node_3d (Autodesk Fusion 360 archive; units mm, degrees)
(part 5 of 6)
sketch "Sketch23" plane through (0, 0, 1.6) normal (0, 0, 1) x axis (-1, 0, 0)
  line L1 (157.1, 69.25) -> (157.1, 89.25)
  line L2 (155.91, 69.25) -> (157.1, 69.25)
  line L3 (155.5, 35.85) -> (155.5, 68.84)
  line L4 (196.59, 27.75) -> (163.6, 27.75)
  line L5 (197, 29.35) -> (197, 28.16)
  line L6 (217, 29.35) -> (197, 29.35)
  line L7 (217, 28.16) -> (217, 29.35)
  line L8 (250.4, 27.75) -> (217.41, 27.75)
  line L9 (258.5, 68.84) -> (258.5, 35.85)
  line L10 (256.9, 69.25) -> (258.09, 69.25)
  line L11 (256.9, 89.25) -> (256.9, 69.25)
  line L12 (258.09, 89.25) -> (256.9, 89.25)
  line L13 (258.5, 122.65) -> (258.5, 89.66)
  line L14 (217.41, 130.75) -> (250.4, 130.75)
  line L15 (217, 129.15) -> (217, 130.34)
  line L16 (197, 129.15) -> (217, 129.15)
  line L17 (197, 130.34) -> (197, 129.15)
  line L18 (163.6, 130.75) -> (196.59, 130.75)
  line L19 (155.5, 89.66) -> (155.5, 122.65)
  line L20 (157.1, 89.25) -> (155.91, 89.25)
  line L21 (208.2, 66.96) -> (208.2, 67.96)
  line L22 (211.35, 66.96) -> (208.2, 66.96)
  line L23 (211.35, 67.96) -> (211.35, 66.96)
  line L24 (208.2, 67.96) -> (211.35, 67.96)
  line L25 (208.2, 69.5) -> (208.2, 70.5)
  line L26 (211.35, 69.5) -> (208.2, 69.5)
  line L27 (211.35, 70.5) -> (211.35, 69.5)
  line L28 (208.2, 70.5) -> (211.35, 70.5)
  line L29 (208.2, 72.04) -> (208.2, 73.04)
  line L30 (211.35, 72.04) -> (208.2, 72.04)
  line L31 (211.35, 73.04) -> (211.35, 72.04)
  line L32 (208.2, 73.04) -> (211.35, 73.04)
  line L33 (204.71, 66.444) -> (204.964, 66.19)
  line L34 (204.964, 66.19) -> (209.536, 66.19)
  line L35 (204.71, 67.14) -> (204.71, 66.444)
  line L36 (204.71, 68.476) -> (204.71, 67.78)
  line L37 (204.964, 68.73) -> (204.71, 68.476)
  line L38 (204.71, 68.984) -> (204.964, 68.73)
  line L39 (204.71, 69.68) -> (204.71, 68.984)
  line L40 (204.71, 71.016) -> (204.71, 70.32)
  line L41 (204.964, 71.27) -> (204.71, 71.016)
  line L42 (204.71, 71.524) -> (204.964, 71.27)
  line L43 (204.71, 72.22) -> (204.71, 71.524)
  line L44 (204.71, 73.556) -> (204.71, 72.86)
  line L45 (204.964, 73.81) -> (204.71, 73.556)
  line L46 (209.536, 73.81) -> (204.964, 73.81)
  line L47 (209.79, 73.556) -> (209.536, 73.81)
  line L48 (209.79, 72.86) -> (209.79, 73.556)
  line L49 (209.79, 71.524) -> (209.79, 72.22)
  line L50 (209.536, 71.27) -> (209.79, 71.524)
  line L51 (209.79, 71.016) -> (209.536, 71.27)
  line L52 (209.79, 70.32) -> (209.79, 71.016)
  line L53 (209.79, 68.984) -> (209.79, 69.68)
  line L54 (209.536, 68.73) -> (209.79, 68.984)
  line L55 (209.79, 68.476) -> (209.536, 68.73)
  line L56 (209.79, 67.78) -> (209.79, 68.476)
  line L57 (209.79, 66.444) -> (209.79, 67.14)
  line L58 (209.536, 66.19) -> (209.79, 66.444)
  line L59 (203.64, 69.68) -> (204.71, 69.68)
  line L60 (203.64, 70.32) -> (204.71, 70.32)
  line L61 (210.86, 69.68) -> (209.79, 69.68)
  line L62 (210.86, 70.32) -> (209.79, 70.32)
  line L63 (210.86, 67.14) -> (209.79, 67.14)
  line L64 (210.86, 67.78) -> (209.79, 67.78)
  line L65 (203.64, 67.78) -> (204.71, 67.78)
  line L66 (203.64, 67.14) -> (204.71, 67.14)
  line L67 (203.64, 72.86) -> (204.71, 72.86)
  line L68 (203.64, 72.22) -> (204.71, 72.22)
  line L69 (210.86, 72.22) -> (209.79, 72.22)
  line L70 (210.86, 72.86) -> (209.79, 72.86)
  line L71 (203.48, 69.84) -> (203.64, 69.68)
  line L72 (203.48, 70.16) -> (203.64, 70.32)
  line L73 (211.02, 69.84) -> (210.86, 69.68)
  line L74 (210.86, 70.32) -> (211.02, 70.16)
  line L75 (211.02, 67.3) -> (210.86, 67.14)
  line L76 (210.86, 67.78) -> (211.02, 67.62)
  line L77 (203.48, 67.62) -> (203.64, 67.78)
  line L78 (203.48, 67.3) -> (203.64, 67.14)
  line L79 (203.48, 72.7) -> (203.64, 72.86)
  line L80 (203.48, 72.38) -> (203.64, 72.22)
  line L81 (211.02, 72.38) -> (210.86, 72.22)
  line L82 (210.86, 72.86) -> (211.02, 72.7)
  line L83 (203.48, 70.16) -> (203.48, 69.84)
  line L84 (211.02, 70.16) -> (211.02, 69.84)
  line L85 (211.02, 67.62) -> (211.02, 67.3)
  line L86 (203.48, 67.62) -> (203.48, 67.3)
  line L87 (203.48, 72.7) -> (203.48, 72.38)
  line L88 (211.02, 72.7) -> (211.02, 72.38)
  line L89 (203.15, 66.96) -> (203.15, 67.96)
  line L90 (206.3, 66.96) -> (203.15, 66.96)
  line L91 (206.3, 67.96) -> (206.3, 66.96)
  line L92 (203.15, 67.96) -> (206.3, 67.96)
  line L93 (203.15, 69.5) -> (203.15, 70.5)
  line L94 (206.3, 69.5) -> (203.15, 69.5)
  line L95 (206.3, 70.5) -> (206.3, 69.5)
  line L96 (203.15, 70.5) -> (206.3, 70.5)
  line L97 (203.15, 72.04) -> (203.15, 73.04)
  line L98 (206.3, 72.04) -> (203.15, 72.04)
  line L99 (206.3, 73.04) -> (206.3, 72.04)
  line L100 (203.15, 73.04) -> (206.3, 73.04)
  line L101 (157.1, 79.25) -> (256.9, 79.25)
  line L102 (207, 29.35) -> (207, 129.15)
  line L103 (189, 97.25) -> (225, 97.25)
  line L104 (189, 61.25) -> (189, 97.25)
  line L105 (225, 61.25) -> (189, 61.25)
  line L106 (225, 97.25) -> (225, 61.25)
  line L107 (189, 61.25) -> (225, 97.25)
  line L108 (225, 61.25) -> (189, 97.25)
  arc A1 centre (155.91, 68.84) radius 0.41 clockwise from (155.5, 68.84) to (155.91, 69.25)
  arc A2 centre (163.6, 35.85) radius 8.1 clockwise from (163.6, 27.75) to (155.5, 35.85)
  arc A3 centre (196.59, 28.16) radius 0.41 clockwise from (197, 28.16) to (196.59, 27.75)
  arc A4 centre (217.41, 28.16) radius 0.41 clockwise from (217.41, 27.75) to (217, 28.16)
  arc A5 centre (250.4, 35.85) radius 8.1 clockwise from (258.5, 35.85) to (250.4, 27.75)
  arc A6 centre (258.09, 68.84) radius 0.41 clockwise from (258.09, 69.25) to (258.5, 68.84)
  arc A7 centre (258.09, 89.66) radius 0.41 clockwise from (258.5, 89.66) to (258.09, 89.25)
  arc A8 centre (250.4, 122.65) radius 8.1 clockwise from (250.4, 130.75) to (258.5, 122.65)
  arc A9 centre (217.41, 130.34) radius 0.41 clockwise from (217, 130.34) to (217.41, 130.75)
  arc A10 centre (196.59, 130.34) radius 0.41 clockwise from (196.59, 130.75) to (197, 130.34)
  arc A11 centre (163.6, 122.65) radius 8.1 clockwise from (155.5, 122.65) to (163.6, 130.75)
  arc A12 centre (155.91, 89.66) radius 0.41 clockwise from (155.91, 89.25) to (155.5, 89.66)
  point P126 (256.9, 79.25)
  point P127 (157.1, 79.25)
  point P128 (207, 129.15)
  point P129 (207, 29.35)
  point P134 (207, 79.25)
  point P132 (189, 61.25)
  point P133 (225, 61.25)
  point P131 (189, 97.25)
  midpoint L11 P126
  midpoint L1 P127
  midpoint L16 P128
  midpoint L6 P129
  horizontal L103
  perpendicular L103 L104
  parallel L103 L105
  parallel L104 L106
  coincident L107 P134
  coincident L108 P134
  midpoint L101 P134
  dimension "d255" distance P132 P133 = 36
  dimension "d256" distance P131 P132 = 36
extrude "Extrude14" new body sketch "body" profile of L1 L2 A1 L3 A2 L4 A3 L5 L6 L7 A4 L8 A5 L9 A6 L10 L11 L12 A7 L13 A8 L14 A9 L15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 along normal blind 20 and against normal blind 8
shell "Shell4" innerThickness 1.5
sketch "supporttoppcb" plane through (0, 0, 0) normal (0, 0, 1) x axis (1, 0, 0)
  line L1 (-258.5, -124.25) -> (-258.5, -34.25)
  line L2 (-159.5, -128.25) -> (-254.5, -128.25)
  line L3 (-155.5, -34.25) -> (-155.5, -124.25)
  line L4 (-254.5, -30.25) -> (-159.5, -30.25)
  line L5 (-163.6, -27.25) -> (-250.4, -27.25)
  line L6 (-155, -122.65) -> (-155, -35.85)
  line L7 (-250.4, -131.25) -> (-163.6, -131.25)
  line L8 (-259, -35.85) -> (-259, -122.65)
  line L9 (-260.5, -122.65) -> (-260.5, -35.85)
  line L10 (-163.6, -132.75) -> (-250.4, -132.75)
  line L11 (-153.5, -35.85) -> (-153.5, -122.65)
  line L12 (-250.4, -25.75) -> (-163.6, -25.75)
  line L13 (-253.0634, -35.85) -> (-253.0634, -122.65)
  line L14 (-163.6, -33.1866) -> (-250.4, -33.1866)
  line L15 (-160.9366, -122.65) -> (-160.9366, -35.85)
  line L16 (-250.4, -125.3134) -> (-163.6, -125.3134)
  line L17 (-259, -41.9011) -> (-253.0634, -41.9011)
  line L18 (-155, -41.9011) -> (-160.9366, -41.9011)
  line L19 (-160.9366, -79.25) -> (-253.0634, -79.25)
  line L20 (-259, -116.5989) -> (-253.0634, -116.5989)
  line L21 (-155, -116.5989) -> (-160.9366, -116.5989)
  line L22 (-253.0634, -79.25) -> (-259, -79.25)
  line L23 (-253.0634, -66.2577) -> (-259, -66.2577)
  line L24 (-253.0634, -92.2423) -> (-259, -92.2423)
  line L25 (-207, -35) -> (-207, -33.1866)
  line L26 (-207, -125.3134) -> (-207, -35)
  line L27 (-160.9366, -66.2577) -> (-155, -66.2577)
  line L28 (-160.9366, -92.2423) -> (-155, -92.2423)
  line L29 (-256, -35.85) -> (-256, -122.65)
  line L30 (-163.6, -30.25) -> (-250.4, -30.25)
  line L31 (-158, -122.65) -> (-158, -35.85)
  line L32 (-250.4, -128.25) -> (-163.6, -128.25)
  line L33 (-223.6065, -33.1866) -> (-223.6065, -27.25)
  line L34 (-190.3935, -33.1866) -> (-190.3935, -27.25)
  line L35 (-223.6065, -125.3134) -> (-223.6065, -131.25)
  line L36 (-190.3935, -125.3134) -> (-190.3935, -131.25)
  arc A1 centre (-254.5, -34.25) radius 4 clockwise from (-258.5, -34.25) to (-254.5, -30.25)
  arc A2 centre (-254.5, -124.25) radius 4 clockwise from (-254.5, -128.25) to (-258.5, -124.25)
  arc A3 centre (-159.5, -124.25) radius 4 clockwise from (-155.5, -124.25) to (-159.5, -128.25)
  arc A4 centre (-159.5, -34.25) radius 4 clockwise from (-159.5, -30.25) to (-155.5, -34.25)
  circle C1 centre (-169.19, -116.29) radius 0.7747
  circle C2 centre (-175.54, -118.83) radius 0.7747
  circle C3 centre (-167.92, -113.75) radius 0.8763
  circle C4 centre (-173, -113.75) radius 2.0447
  circle C5 centre (-178.08, -113.75) radius 0.8763
  circle C6 centre (-202.44, -116.29) radius 0.7747
  circle C7 centre (-201.17, -113.75) radius 0.8763
  circle C8 centre (-206.25, -113.75) radius 2.0447
  circle C9 centre (-169.19, -82.29) radius 0.7747
  circle C10 centre (-175.54, -84.83) radius 0.7747
  circle C11 centre (-203.11, -82.29) radius 0.7747
  circle C12 centre (-208.79, -118.83) radius 0.7747
  circle C13 centre (-211.33, -113.75) radius 0.8763
  circle C14 centre (-237.17, -113.75) radius 0.8763
  circle C15 centre (-238.44, -116.29) radius 0.7747
  circle C16 centre (-244.79, -118.83) radius 0.7747
  circle C17 centre (-242.25, -113.75) radius 2.0447
  circle C18 centre (-247.33, -113.75) radius 0.8763
  circle C19 centre (-209.46, -84.83) radius 0.7747
  circle C20 centre (-237.61, -82.29) radius 0.7747
  circle C21 centre (-243.96, -84.83) radius 0.7747
  circle C22 centre (-167.92, -79.75) radius 0.8763
  circle C23 centre (-173, -79.75) radius 2.0447
  circle C24 centre (-178.08, -79.75) radius 0.8763
  circle C25 centre (-201.84, -79.75) radius 0.8763
  circle C26 centre (-206.92, -79.75) radius 2.0447
  circle C27 centre (-175.54, -50.83) radius 0.7747
  circle C28 centre (-169.19, -48.29) radius 0.7747
  circle C29 centre (-167.92, -45.75) radius 0.8763
  circle C30 centre (-173, -45.75) radius 2.0447
  circle C31 centre (-178.08, -45.75) radius 0.8763
  circle C32 centre (-202.09, -45.75) radius 0.8763
  circle C33 centre (-203.36, -48.29) radius 0.7747
  circle C34 centre (-207.17, -45.75) radius 2.0447
  circle C35 centre (-212, -79.75) radius 0.8763
  circle C36 centre (-236.34, -79.75) radius 0.8763
  circle C37 centre (-241.42, -79.75) radius 2.0447
  circle C38 centre (-246.5, -79.75) radius 0.8763
  circle C39 centre (-209.71, -50.83) radius 0.7747
  circle C40 centre (-212.25, -45.75) radius 0.8763
  circle C41 centre (-237.34, -45.75) radius 0.8763
  circle C42 centre (-244.96, -50.83) radius 0.7747
  circle C43 centre (-238.61, -48.29) radius 0.7747
  circle C44 centre (-242.42, -45.75) radius 2.0447
  circle C45 centre (-247.5, -45.75) radius 0.8763
  arc A5 centre (-163.6, -35.85) radius 8.6 clockwise from (-163.6, -27.25) to (-155, -35.85)
  arc A6 centre (-163.6, -122.65) radius 8.6 clockwise from (-155, -122.65) to (-163.6, -131.25)
  arc A7 centre (-250.4, -122.65) radius 8.6 clockwise from (-250.4, -131.25) to (-259, -122.65)
  arc A8 centre (-250.4, -35.85) radius 8.6 clockwise from (-259, -35.85) to (-250.4, -27.25)
  arc A9 centre (-250.4, -35.85) radius 10.1 clockwise from (-260.5, -35.85) to (-250.4, -25.75)
  arc A10 centre (-250.4, -122.65) radius 10.1 clockwise from (-250.4, -132.75) to (-260.5, -122.65)
  arc A11 centre (-163.6, -122.65) radius 10.1 clockwise from (-153.5, -122.65) to (-163.6, -132.75)
  arc A12 centre (-163.6, -35.85) radius 10.1 clockwise from (-163.6, -25.75) to (-153.5, -35.85)
  arc A13 centre (-250.4, -35.85) radius 2.6634 clockwise from (-253.0634, -35.85) to (-250.4, -33.1866)
  arc A14 centre (-163.6, -35.85) radius 2.6634 clockwise from (-163.6, -33.1866) to (-160.9366, -35.85)
  arc A15 centre (-163.6, -122.65) radius 2.6634 clockwise from (-160.9366, -122.65) to (-163.6, -125.3134)
  arc A16 centre (-250.4, -122.65) radius 2.6634 clockwise from (-250.4, -125.3134) to (-253.0634, -122.65)
  arc A17 centre (-250.4, -35.85) radius 5.6 clockwise from (-256, -35.85) to (-250.4, -30.25)
  arc A18 centre (-163.6, -35.85) radius 5.6 clockwise from (-163.6, -30.25) to (-158, -35.85)
  arc A19 centre (-163.6, -122.65) radius 5.6 clockwise from (-158, -122.65) to (-163.6, -128.25)
  arc A20 centre (-250.4, -122.65) radius 5.6 clockwise from (-250.4, -128.25) to (-256, -122.65)
  point P95 (-253.0634, -41.9011)
  point P96 (-259, -41.9011)
  point P97 (-160.9366, -41.9011)
  point P98 (-155, -41.9011)
  point P99 (-253.0634, -79.25)
  point P100 (-160.9366, -79.25)
  point P101 (-253.0634, -116.5989)
  point P102 (-259, -116.5989)
  point P103 (-160.9366, -116.5989)
  point P104 (-155, -116.5989)
  point P105 (-259, -79.25)
  point P110 (-207, -33.1866)
  point P112 (-207, -125.3134)
  point P106 (-259, -66.2577)
  point P113 (-155, -66.2577)
  point P107 (-253.0634, -66.2577)
  point P114 (-160.9366, -66.2577)
  point P108 (-259, -92.2423)
  point P115 (-155, -92.2423)
  point P109 (-253.0634, -92.2423)
  point P116 (-160.9366, -92.2423)
  point P129 (-223.6065, -27.25)
  point P130 (-223.6065, -33.1866)
  point P131 (-190.3935, -27.25)
  point P132 (-190.3935, -33.1866)
  point P133 (-223.6065, -131.25)
  point P134 (-223.6065, -125.3134)
  point P135 (-190.3935, -131.25)
  point P136 (-190.3935, -125.3134)
  coincident L13 P95
  coincident L8 P96
  perpendicular L8 L17
  coincident L15 P97
  coincident L6 P98
  perpendicular L6 L18
  midpoint L13 P99
  midpoint L15 P100
  perpendicular L15 L19
  symmetric P95 L19 P101
  symmetric P96 L19 P102
  symmetric P97 L19 P103
  symmetric P98 L19 P104
  midpoint L8 P105
  perpendicular L13 L22
  midpoint L14 P110
  perpendicular L14 L25
  midpoint L16 P112
  perpendicular L16 L26
  symmetric P106 L26 P113
  symmetric P107 L26 P114
  symmetric P108 L26 P115
  symmetric P109 L26 P116
  coincident L5 P129
  coincident L14 P130
  perpendicular L14 L33
  symmetric L26 P129 P131
  symmetric L26 P130 P132
  symmetric L19 P129 P133
  symmetric L19 P130 P134
  symmetric L19 P131 P135
  symmetric L19 P132 P136
  dimension "d175" = -5.9366
  dimension "d179" = -12.9923
  dimension "d180" = 12.9923
  dimension "d193" = -3
sketch "Sketch20" plane through (0, -27.25, 0) normal (0, -1, 0) x axis (1, 0, 0)
  line L1 (-250.4, -6.5) -> (-250.4, 20)
  line L2 (-163.6, -6.5) -> (-250.4, -6.5)
  line L3 (-163.6, 20) -> (-163.6, -6.5)
  line L4 (-250.4, 20) -> (-163.6, 20)
  line L5 (-212.93, 3.24) -> (-212.93, -1.64)
  line L6 (-211.23, -1.64) -> (-211.23, 3.24)
  line L7 (-202.77, 3.24) -> (-202.77, -1.64)
  line L8 (-201.07, -1.64) -> (-201.07, 3.24)
  line L9 (-210.39, 3.24) -> (-210.39, -1.64)
  line L10 (-208.69, -1.64) -> (-208.69, 3.24)
  line L11 (-205.31, 3.24) -> (-205.31, -1.64)
  line L12 (-203.61, -1.64) -> (-203.61, 3.24)
  line L13 (-207.85, 3.24) -> (-207.85, -1.64)
  line L14 (-206.15, -1.64) -> (-206.15, 3.24)
  line L15 (-221, 1.8) -> (-221, 2.8)
  line L16 (-216.8, 1.8) -> (-221, 1.8)
  line L17 (-216.8, -0.2) -> (-216.8, 1.8)
  line L18 (-221, -0.2) -> (-216.8, -0.2)
  line L19 (-221, -1.2) -> (-221, -0.2)
  line L20 (-196, -4.2) -> (-218, -4.2)
  line L21 (-193, -0.2) -> (-193, -1.2)
  line L22 (-197.2, -0.2) -> (-193, -0.2)
  line L23 (-197.2, 1.8) -> (-197.2, -0.2)
  line L24 (-193, 1.8) -> (-197.2, 1.8)
  line L25 (-193, 2.8) -> (-193, 1.8)
  line L26 (-218, 5.8) -> (-196, 5.8)
  line L27 (-223, 1.8) -> (-223, 2.8)
  line L28 (-223, -0.2) -> (-223, 1.8)
  line L29 (-223, -1.2) -> (-223, -0.2)
  line L30 (-196, -6.2) -> (-218, -6.2)
  line L31 (-191, -0.2) -> (-191, -1.2)
  line L32 (-191, 1.8) -> (-191, -0.2)
  line L33 (-191, 2.8) -> (-191, 1.8)
  line L34 (-218, 7.8) -> (-196, 7.8)
  line L35 (-207, -4.2) -> (-207, 5.8)
  line L36 (-215, -4.2) -> (-215, 5.8)
  line L37 (-199, -4.2) -> (-199, 5.8)
  line L38 (-199, -6.2) -> (-199, -4.2)
  line L39 (-215, -6.2) -> (-215, -4.2)
  line L40 (-217, 1.6) -> (-221.2, 1.6)
  line L41 (-217, 0) -> (-217, 1.6)
  line L42 (-221.2, 0) -> (-217, 0)
  line L43 (-221.2, -1.2) -> (-221.2, 0)
  line L44 (-196, -4.4) -> (-218, -4.4)
  line L45 (-192.8, 0) -> (-192.8, -1.2)
  line L46 (-197, 0) -> (-192.8, 0)
  line L47 (-197, 1.6) -> (-197, 0)
  line L48 (-192.8, 1.6) -> (-197, 1.6)
  line L49 (-192.8, 2.8) -> (-192.8, 1.6)
  line L50 (-218, 6) -> (-196, 6)
  line L51 (-221.2, 1.6) -> (-221.2, 2.8)
  line L52 (-221.5, 1.3) -> (-221.5, 2.8)
  line L53 (-217.3, 1.3) -> (-221.5, 1.3)
  line L54 (-217.3, 0.3) -> (-217.3, 1.3)
  line L55 (-221.5, 0.3) -> (-217.3, 0.3)
  line L56 (-221.5, -1.2) -> (-221.5, 0.3)
  line L57 (-196, -4.7) -> (-218, -4.7)
  line L58 (-192.5, 0.3) -> (-192.5, -1.2)
  line L59 (-196.7, 0.3) -> (-192.5, 0.3)
  line L60 (-196.7, 1.3) -> (-196.7, 0.3)
  line L61 (-192.5, 1.3) -> (-196.7, 1.3)
  line L62 (-192.5, 2.8) -> (-192.5, 1.3)
  line L63 (-218, 6.3) -> (-196, 6.3)
  line L64 (-224.9282, -2.2) -> (-225, -2.2)
  line L65 (-196, -8.2) -> (-218, -8.2)
  line L66 (-189, -2.2) -> (-189.0718, -2.2)
  line L67 (-189, -1.2) -> (-189, -2.2)
  line L68 (-189, 2.8) -> (-189, -1.2)
  line L69 (-189, 3.8) -> (-189, 2.8)
  line L70 (-189.0718, 3.8) -> (-189, 3.8)
  line L71 (-218, 9.8) -> (-196, 9.8)
  line L72 (-225, 3.8) -> (-224.9282, 3.8)
  line L73 (-225, 2.8) -> (-225, 3.8)
  line L74 (-225, -1.2) -> (-225, 2.8)
  line L75 (-225, -2.2) -> (-225, -1.2)
  line L76 (-225, -1.1) -> (-221, -1.1)
  line L77 (-189, -1.1) -> (-193, -1.1)
  arc A1 centre (-212.08, -1.64) radius 0.85 clockwise from (-211.23, -1.64) to (-212.93, -1.64)
  arc A2 centre (-212.08, 3.24) radius 0.85 clockwise from (-212.93, 3.24) to (-211.23, 3.24)
  arc A3 centre (-201.92, -1.64) radius 0.85 clockwise from (-201.07, -1.64) to (-202.77, -1.64)
  arc A4 centre (-201.92, 3.24) radius 0.85 clockwise from (-202.77, 3.24) to (-201.07, 3.24)
  arc A5 centre (-209.54, -1.64) radius 0.85 clockwise from (-208.69, -1.64) to (-210.39, -1.64)
  arc A6 centre (-209.54, 3.24) radius 0.85 clockwise from (-210.39, 3.24) to (-208.69, 3.24)
  arc A7 centre (-204.46, -1.64) radius 0.85 clockwise from (-203.61, -1.64) to (-205.31, -1.64)
  arc A8 centre (-204.46, 3.24) radius 0.85 clockwise from (-205.31, 3.24) to (-203.61, 3.24)
  arc A9 centre (-207, -1.64) radius 0.85 clockwise from (-206.15, -1.64) to (-207.85, -1.64)
  arc A10 centre (-207, 3.24) radius 0.85 clockwise from (-207.85, 3.24) to (-206.15, 3.24)
  arc A11 centre (-218, 2.8) radius 3 clockwise from (-221, 2.8) to (-218, 5.8)
  arc A12 centre (-218, -1.2) radius 3 clockwise from (-218, -4.2) to (-221, -1.2)
  arc A13 centre (-196, -1.2) radius 3 clockwise from (-193, -1.2) to (-196, -4.2)
  arc A14 centre (-196, 2.8) radius 3 clockwise from (-196, 5.8) to (-193, 2.8)
  arc A15 centre (-218, -1.2) radius 5 clockwise from (-218, -6.2) to (-223, -1.2)
  arc A16 centre (-196, -1.2) radius 5 clockwise from (-191, -1.2) to (-196, -6.2)
  arc A17 centre (-196, 2.8) radius 5 clockwise from (-196, 7.8) to (-191, 2.8)
  arc A18 centre (-218, 2.8) radius 5 clockwise from (-223, 2.8) to (-218, 7.8)
  arc A19 centre (-218, -1.2) radius 3.2 clockwise from (-218, -4.4) to (-221.2, -1.2)
  arc A20 centre (-196, -1.2) radius 3.2 clockwise from (-192.8, -1.2) to (-196, -4.4)
  arc A21 centre (-196, 2.8) radius 3.2 clockwise from (-196, 6) to (-192.8, 2.8)
  arc A22 centre (-218, 2.8) radius 3.2 clockwise from (-221.2, 2.8) to (-218, 6)
  arc A23 centre (-218, -1.2) radius 3.5 clockwise from (-218, -4.7) to (-221.5, -1.2)
  arc A24 centre (-196, -1.2) radius 3.5 clockwise from (-192.5, -1.2) to (-196, -4.7)
  arc A25 centre (-196, 2.8) radius 3.5 clockwise from (-196, 6.3) to (-192.5, 2.8)
  arc A26 centre (-218, 2.8) radius 3.5 clockwise from (-221.5, 2.8) to (-218, 6.3)
  arc A27 centre (-218, -1.2) radius 7 clockwise from (-218, -8.2) to (-224.9282, -2.2)
  arc A28 centre (-196, -1.2) radius 7 clockwise from (-189.0718, -2.2) to (-196, -8.2)
  arc A29 centre (-196, 2.8) radius 7 clockwise from (-196, 9.8) to (-189.0718, 3.8)
  arc A30 centre (-218, 2.8) radius 7 clockwise from (-224.9282, 3.8) to (-218, 9.8)
  point P72 (-207, 5.8)
  point P73 (-207, -4.2)
  point P78 (-199, -6.2)
  point P79 (-215, -6.2)
  point P140 (-221, -1.1)
  point P141 (-225, -1.1)
  point P142 (-193, -1.1)
  point P143 (-189, -1.1)
  midpoint L26 P72
  midpoint L20 P73
  coincident L30 P78
  perpendicular L30 L38
  coincident L30 P79
  perpendicular L30 L39
  coincident L19 P140
  coincident L74 P141
  perpendicular L74 L76
  symmetric L35 P140 P142
  symmetric L35 P141 P143
  dimension "d234" = 2
  dimension "d235" = 8
  dimension "d236" = -8
  dimension "d237" = 0.2
  dimension "d240" = 0.5
  dimension "d241" = 4
extrude "Extrude22" new body sketch "Sketch20" profile of L32 L34 L28 A17 L29 L30 A15 L33 A18 A16 L38 L39 L55 L59 L52 L57 A26 L53 L54 L62 A23 L60 A24 L61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 along normal blind 2
extrude "Extrude23" new body sketch "Sketch20" profile of L32 L34 L28 A17 L29 L33 A18 L48 L41 L49 L40 A22 L42 L46 L51 L43 A21 L45 L50 L47 L55 L59 L52 A26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 blind 3 from offset 0.2
combine "Combine5"
extrude "Extrude16" sketch "supporttoppcb" profile of A1 L1 A2 L2 A3 L3 A4 L4 L5 A5 L6 A6 L7 A7 L8 A8 L17 L18 L20 L21 L23 L24 L27 L28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 blind -3
combine "Combine3"
sketch "Sketch17" plane through (0, 0, 0) normal (0, 0, 1) x axis (1, 0, 0)
  line L1 (-250.4, -27.75) -> (-163.6, -27.75)
  line L2 (-258.5, -122.65) -> (-258.5, -35.85)
  line L3 (-163.6, -130.75) -> (-250.4, -130.75)
  line L4 (-155.5, -35.85) -> (-155.5, -122.65)
  line L5 (-255.5, -122.65) -> (-255.5, -35.85)
  line L6 (-163.6, -127.75) -> (-250.4, -127.75)
  line L7 (-158.5, -35.85) -> (-158.5, -122.65)
  line L8 (-250.4, -30.75) -> (-163.6, -30.75)
  line L9 (-288.9329, -64.1731) -> (-300.7329, -64.1731)
  line L10 (-288.9329, -72.9131) -> (-288.9329, -64.1731)
  line L11 (-300.7329, -72.9131) -> (-288.9329, -72.9131)
  line L12 (-300.7329, -64.1731) -> (-300.7329, -72.9131)
  line L13 (-207, -127.75) -> (-207, -30.75)
  line L14 (-161.2828, -79.25) -> (-158.5, -79.25)
  line L15 (-255.5, -79.25) -> (-161.2828, -79.25)
  line L16 (-205.825, -66.92) -> (-205.825, -67.92)
  line L17 (-209.061, -73.77) -> (-209.315, -73.516)
  line L18 (-209.061, -71.23) -> (-209.315, -70.976)
  line L19 (-210.875, -69.46) -> (-210.875, -70.46)
  line L20 (-209.315, -70.976) -> (-209.315, -70.28)
  line L21 (-204.235, -72.82) -> (-203.165, -72.82)
  line L22 (-209.315, -66.404) -> (-209.061, -66.15)
  line L23 (-203.005, -72.66) -> (-203.005, -72.34)
  line L24 (-204.489, -73.77) -> (-209.061, -73.77)
  line L25 (-210.875, -70.46) -> (-207.725, -70.46)
  line L26 (-204.235, -67.74) -> (-203.165, -67.74)
  line L27 (-209.061, -66.15) -> (-204.489, -66.15)
  line L28 (-209.315, -70.28) -> (-210.385, -70.28)
  line L29 (-204.489, -71.23) -> (-204.235, -71.484)
  line L30 (-203.165, -67.74) -> (-203.005, -67.58)
  line L31 (-207.725, -66.92) -> (-210.875, -66.92)
  line L32 (-209.315, -67.74) -> (-210.385, -67.74)
  line L33 (-204.235, -67.1) -> (-203.165, -67.1)
  line L34 (-210.875, -73) -> (-207.725, -73)
  line L35 (-209.061, -68.69) -> (-209.315, -68.436)
  line L36 (-210.545, -70.12) -> (-210.545, -69.8)
  line L37 (-205.825, -72) -> (-205.825, -73)
  line L38 (-210.875, -66.92) -> (-210.875, -67.92)
  line L39 (-202.675, -72) -> (-205.825, -72)
  line L40 (-203.005, -67.58) -> (-203.005, -67.26)
  line L41 (-205.825, -67.92) -> (-202.675, -67.92)
  line L42 (-203.165, -70.28) -> (-203.005, -70.12)
  line L43 (-203.005, -69.8) -> (-203.165, -69.64)
  line L44 (-209.315, -68.944) -> (-209.061, -68.69)
  line L45 (-203.005, -72.34) -> (-203.165, -72.18)
  line L46 (-210.545, -67.26) -> (-210.385, -67.1)
  line L47 (-204.235, -70.28) -> (-203.165, -70.28)
  line L48 (-204.235, -71.484) -> (-204.235, -72.18)
  line L49 (-204.489, -66.15) -> (-204.235, -66.404)
  line L50 (-209.315, -72.82) -> (-210.385, -72.82)
  line L51 (-209.315, -73.516) -> (-209.315, -72.82)
  line L52 (-209.315, -71.484) -> (-209.061, -71.23)
  line L53 (-204.235, -69.64) -> (-203.165, -69.64)
  line L54 (-210.545, -72.34) -> (-210.385, -72.18)
  line L55 (-207.725, -67.92) -> (-207.725, -66.92)
  line L56 (-210.875, -72) -> (-210.875, -73)
  line L57 (-207.725, -69.46) -> (-210.875, -69.46)
  line L58 (-204.235, -70.28) -> (-204.235, -70.976)
  line L59 (-202.675, -67.92) -> (-202.675, -66.92)
  line L60 (-202.675, -66.92) -> (-205.825, -66.92)
  line L61 (-203.005, -67.26) -> (-203.165, -67.1)
  line L62 (-209.315, -68.436) -> (-209.315, -67.74)
  line L63 (-210.545, -67.58) -> (-210.545, -67.26)
  line L64 (-210.875, -67.92) -> (-207.725, -67.92)
  line L65 (-204.235, -68.944) -> (-204.235, -69.64)
  line L66 (-204.235, -72.82) -> (-204.235, -73.516)
  line L67 (-204.235, -68.436) -> (-204.489, -68.69)
  line L68 (-204.235, -73.516) -> (-204.489, -73.77)
  line L69 (-204.235, -70.976) -> (-204.489, -71.23)
  line L70 (-203.165, -72.82) -> (-203.005, -72.66)
  line L71 (-204.235, -72.18) -> (-203.165, -72.18)
  line L72 (-204.235, -67.74) -> (-204.235, -68.436)
  line L73 (-210.385, -70.28) -> (-210.545, -70.12)
  line L74 (-202.675, -70.46) -> (-202.675, -69.46)
  line L75 (-204.235, -66.404) -> (-204.235, -67.1)
  line L76 (-210.545, -72.66) -> (-210.545, -72.34)
  line L77 (-205.825, -73) -> (-202.675, -73)
  line L78 (-210.385, -67.74) -> (-210.545, -67.58)
  line L79 (-207.725, -73) -> (-207.725, -72)
  line L80 (-202.675, -69.46) -> (-205.825, -69.46)
  line L81 (-209.315, -69.64) -> (-210.385, -69.64)
  line L82 (-203.005, -70.12) -> (-203.005, -69.8)
  line L83 (-209.315, -72.18) -> (-210.385, -72.18)
  line L84 (-205.825, -70.46) -> (-202.675, -70.46)
  line L85 (-205.825, -69.46) -> (-205.825, -70.46)
  line L86 (-209.315, -67.1) -> (-210.385, -67.1)
  line L87 (-204.489, -68.69) -> (-204.235, -68.944)
  line L88 (-210.545, -69.8) -> (-210.385, -69.64)
  line L89 (-207.725, -70.46) -> (-207.725, -69.46)
  line L90 (-209.315, -67.1) -> (-209.315, -66.404)
  line L91 (-209.315, -69.64) -> (-209.315, -68.944)
  line L92 (-210.385, -72.82) -> (-210.545, -72.66)
  line L93 (-207.725, -72) -> (-210.875, -72)
  line L94 (-202.675, -73) -> (-202.675, -72)
  line L95 (-209.315, -72.18) -> (-209.315, -71.484)
  arc A1 centre (-163.6, -35.85) radius 8.1 clockwise from (-163.6, -27.75) to (-155.5, -35.85)
  arc A2 centre (-250.4, -35.85) radius 8.1 clockwise from (-258.5, -35.85) to (-250.4, -27.75)
  arc A3 centre (-250.4, -122.65) radius 8.1 clockwise from (-250.4, -130.75) to (-258.5, -122.65)
  arc A4 centre (-163.6, -122.65) radius 8.1 clockwise from (-155.5, -122.65) to (-163.6, -130.75)
  arc A5 centre (-250.4, -122.65) radius 5.1 clockwise from (-250.4, -127.75) to (-255.5, -122.65)
  arc A6 centre (-163.6, -122.65) radius 5.1 clockwise from (-158.5, -122.65) to (-163.6, -127.75)
  arc A7 centre (-163.6, -35.85) radius 5.1 clockwise from (-163.6, -30.75) to (-158.5, -35.85)
  arc A8 centre (-250.4, -35.85) radius 5.1 clockwise from (-255.5, -35.85) to (-250.4, -30.75)
  point P30 (-207, -30.75)
  point P31 (-207, -127.75)
  point P32 (-158.5, -79.25)
  point P34 (-255.5, -79.25)
  point P26 (-300.7329, -64.1731)
  point P29 (-300.7329, -72.9131)
  horizontal L9
  vertical L10
  horizontal L11
  vertical L12
  midpoint L8 P30
  midpoint L6 P31
  perpendicular L6 L13
  midpoint L7 P32
  perpendicular L7 L14
  midpoint L5 P34
  perpendicular L5 L15
  dimension "d184" = -3
  dimension "d185" distance L10 L12 = 11.8
  dimension "d186" distance P26 P29 = 8.74
extrude "Extrude17" sketch "Sketch17" profile of A1 L1 A2 L2 A3 L3 A4 L4 L5 A6 A7 L6 A8 L8 L7 A5 blind -3
fillet "Fillet4" radius 5
extrude "Extrude18" cut sketch "Sketch10" profile of C1 L1 L2 C2 L3 L4 C3 L5 L6 C4 L7 L8 C5 L9 L10 L11 L12 A11 A12 A13 A14 distance -135
sketch "Sketch18" plane through (-153.5, 0, 0) normal (1, 0, 0) x axis (0, 1, 0)
  line L1 (-35.85, -3) -> (-122.65, -3)
  line L2 (-35.85, 20) -> (-35.85, -3)
  line L3 (-122.65, 20) -> (-35.85, 20)
  line L4 (-122.65, -3) -> (-122.65, 20)
  line L5 (-35.85, -8) -> (-30.75, -8)
  line L6 (-127.75, -8) -> (-122.65, -8)
  line L7 (-122.65, -8) -> (-35.85, -8)
  line L8 (-25.75, -3) -> (-25.75, 20)
  line L9 (-35.85, 20) -> (-25.75, 20)
  line L10 (-132.75, 20) -> (-132.75, -3)
  line L11 (-132.75, 20) -> (-122.65, 20)
  line L12 (-122.65, 20) -> (-35.85, 20)
  line L13 (-83.48, 3.24) -> (-83.48, -1.64)
  line L14 (-85.18, -1.64) -> (-85.18, 3.24)
  line L15 (-73.32, 3.24) -> (-73.32, -1.64)
  line L16 (-75.02, -1.64) -> (-75.02, 3.24)
  line L17 (-74.32, 2.3) -> (-84.18, 2.3)
  line L18 (-84.18, -0.7) -> (-74.32, -0.7)
  line L19 (-73.32, 3.24) -> (-73.32, -1.64)
  line L20 (-75.02, -1.64) -> (-75.02, 3.24)
  arc A1 centre (-30.75, -3) radius 5 clockwise from (-25.75, -3) to (-30.75, -8)
  arc A2 centre (-127.75, -3) radius 5 clockwise from (-127.75, -8) to (-132.75, -3)
  circle C1 centre (-84.33, 0.8) radius 0.5
  arc A3 centre (-84.33, 3.24) radius 0.85 clockwise from (-85.18, 3.24) to (-83.48, 3.24)
  arc A4 centre (-84.33, -1.64) radius 0.85 clockwise from (-83.48, -1.64) to (-85.18, -1.64)
  circle C2 centre (-74.17, 0.8) radius 0.5
  arc A5 centre (-74.17, 3.24) radius 0.85 clockwise from (-75.02, 3.24) to (-73.32, 3.24)
  arc A6 centre (-74.17, -1.64) radius 0.85 clockwise from (-73.32, -1.64) to (-75.02, -1.64)
  arc A7 centre (-74.32, 0.8) radius 1.5 clockwise from (-74.32, 2.3) to (-72.82, 0.8)
  arc A8 centre (-84.18, 0.8) radius 1.5 clockwise from (-85.68, 0.8) to (-84.18, 2.3)
  arc A9 centre (-84.18, 0.8) radius 1.5 clockwise from (-84.18, -0.7) to (-85.68, 0.8)
  arc A10 centre (-74.32, 0.8) radius 1.5 clockwise from (-72.82, 0.8) to (-74.32, -0.7)
  arc A11 centre (-74.17, 3.24) radius 0.85 clockwise from (-75.02, 3.24) to (-73.32, 3.24)
  arc A12 centre (-74.17, -1.64) radius 0.85 clockwise from (-73.32, -1.64) to (-75.02, -1.64)
  point P35 (-72.82, 0.8)
  point P49 (-72.82, 0.8)
  point P40 (-85.68, 0.8)
  point P45 (-85.68, 0.8)
  horizontal L18
  horizontal L17
  tangent L18 A10
  tangent A7 L17
  equal A7 A10
  coincident P35 P49
  tangent A9 L18
  tangent L17 A8
  equal A8 A9
  coincident P40 P45
  dimension "d208" radius A10 = 1.5
  dimension "d209" radius A9 = 1.5
extrude "Extrude19" cut sketch "Sketch18" profile of C1 L13 L14 C2 L15 L16 A7 L17 A8 A9 L18 A10 L19 L20 along normal blind 5 and against normal blind 180
component_from_bodies "Body->Comp4"
sketch "Sketch19" plane through (-258.5, 0, 0) normal (-1, 0, 0) x axis (0, -1, 0)
  line L1 (122.65, 0) -> (89.66, 0)
  line L2 (122.65, 1.6) -> (122.65, 0)
  line L3 (89.66, 1.6) -> (122.65, 1.6)
  line L4 (89.66, 0) -> (89.66, 1.6)
  line L5 (68.84, 0) -> (35.85, 0)
  line L6 (68.84, 1.6) -> (68.84, 0)
  line L7 (35.85, 1.6) -> (68.84, 1.6)
  line L8 (35.85, 0) -> (35.85, 1.6)
  line L9 (85.18, 3.24) -> (85.18, -1.64)
  line L10 (69.45, 1.8) -> (65.25, 1.8)
  line L11 (78.4, 3.24) -> (78.4, -1.64)
  line L12 (82.64, 3.24) -> (82.64, -1.64)
  line L13 (77.56, -1.64) -> (77.56, 3.24)
  line L14 (69.45, -0.2) -> (69.45, 1.8)
  line L15 (83.48, 3.24) -> (83.48, -1.64)
  line L16 (65.25, -0.2) -> (69.45, -0.2)
  line L17 (80.94, 3.24) -> (80.94, -1.64)
  line L18 (82.64, -1.64) -> (82.64, 3.24)
  line L19 (89.05, -0.2) -> (93.25, -0.2)
  line L20 (78.4, -1.64) -> (78.4, 3.24)
  line L21 (75.02, 3.24) -> (75.02, -1.64)
  line L22 (93.25, -0.2) -> (93.25, -1.2)
  line L23 (80.1, -1.64) -> (80.1, 3.24)
  line L24 (75.86, 3.24) -> (75.86, -1.64)
  line L25 (73.32, -1.64) -> (73.32, 3.24)
  line L26 (83.48, -1.64) -> (83.48, 3.24)
  line L27 (75.02, -1.64) -> (75.02, 3.24)
  line L28 (65.25, -1.2) -> (65.25, -0.2)
  line L29 (65.25, 1.8) -> (65.25, 2.8)
  line L30 (85.18, -1.64) -> (85.18, 3.24)
  line L31 (68.25, 5.8) -> (90.25, 5.8)
  line L32 (77.56, 3.24) -> (77.56, -1.64)
  line L33 (89.05, 1.8) -> (89.05, -0.2)
  line L34 (90.25, -4.2) -> (68.25, -4.2)
  line L35 (93.25, 1.8) -> (89.05, 1.8)
  line L36 (80.1, 3.24) -> (80.1, -1.64)
  line L37 (73.32, 3.24) -> (73.32, -1.64)
  line L38 (35.85, 0) -> (35.85, 1.6)
  line L39 (93.25, 2.8) -> (93.25, 1.8)
  line L40 (68.84, 1.6) -> (68.84, 0)
  line L41 (68.84, 0) -> (35.85, 0)
  line L42 (35.85, 1.6) -> (68.84, 1.6)
  line L43 (75.86, -1.64) -> (75.86, 3.24)
  line L44 (80.94, -1.64) -> (80.94, 3.24)
  arc A1 centre (76.71, 3.24) radius 0.85 clockwise from (75.86, 3.24) to (77.56, 3.24)
  arc A2 centre (76.71, -1.64) radius 0.85 clockwise from (77.56, -1.64) to (75.86, -1.64)
  arc A3 centre (81.79, -1.64) radius 0.85 clockwise from (82.64, -1.64) to (80.94, -1.64)
  circle C1 centre (76.71, 0.8) radius 0.5
  arc A4 centre (84.33, 3.24) radius 0.85 clockwise from (83.48, 3.24) to (85.18, 3.24)
  arc A5 centre (68.25, -1.2) radius 3 clockwise from (68.25, -4.2) to (65.25, -1.2)
  circle C2 centre (84.33, 0.8) radius 0.5
  arc A6 centre (84.33, -1.64) radius 0.85 clockwise from (85.18, -1.64) to (83.48, -1.64)
  arc A7 centre (84.33, -1.64) radius 0.85 clockwise from (85.18, -1.64) to (83.48, -1.64)
  arc A8 centre (74.17, 3.24) radius 0.85 clockwise from (73.32, 3.24) to (75.02, 3.24)
  arc A9 centre (81.79, 3.24) radius 0.85 clockwise from (80.94, 3.24) to (82.64, 3.24)
  arc A10 centre (79.25, 3.24) radius 0.85 clockwise from (78.4, 3.24) to (80.1, 3.24)
  arc A11 centre (79.25, -1.64) radius 0.85 clockwise from (80.1, -1.64) to (78.4, -1.64)
  circle C3 centre (74.17, 0.8) radius 0.5
  arc A12 centre (74.17, -1.64) radius 0.85 clockwise from (75.02, -1.64) to (73.32, -1.64)
  arc A13 centre (74.17, 3.24) radius 0.85 clockwise from (73.32, 3.24) to (75.02, 3.24)
  arc A14 centre (74.17, -1.64) radius 0.85 clockwise from (75.02, -1.64) to (73.32, -1.64)
  arc A15 centre (68.25, 2.8) radius 3 clockwise from (65.25, 2.8) to (68.25, 5.8)
  arc A16 centre (84.33, 3.24) radius 0.85 clockwise from (83.48, 3.24) to (85.18, 3.24)
  arc A17 centre (76.71, -1.64) radius 0.85 clockwise from (77.56, -1.64) to (75.86, -1.64)
  arc A18 centre (76.71, 3.24) radius 0.85 clockwise from (75.86, 3.24) to (77.56, 3.24)
  arc A19 centre (90.25, 2.8) radius 3 clockwise from (90.25, 5.8) to (93.25, 2.8)
  circle C4 centre (81.79, 0.8) radius 0.5
  arc A20 centre (90.25, -1.2) radius 3 clockwise from (93.25, -1.2) to (90.25, -4.2)
  arc A21 centre (81.79, -1.64) radius 0.85 clockwise from (82.64, -1.64) to (80.94, -1.64)
  arc A22 centre (79.25, -1.64) radius 0.85 clockwise from (80.1, -1.64) to (78.4, -1.64)
  arc A23 centre (79.25, 3.24) radius 0.85 clockwise from (78.4, 3.24) to (80.1, 3.24)
  arc A24 centre (81.79, 3.24) radius 0.85 clockwise from (80.94, 3.24) to (82.64, 3.24)
  circle C5 centre (79.25, 0.8) radius 0.5
extrude "Extrude20" new body sketch "Sketch19" profile of A1 A2 L9 A3 C1 A4 L10 L11 A5 L12 L13 L14 L15 L16 C2 A6 L17 L18 A7 A8 L19 L20 A9 L21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 against normal blind 1.6
extrude "Extrude21" new body sketch "Sketch19" profile of A1 A2 L9 A3 C1 A4 L11 L12 L13 L15 C2 A6 L17 L18 A7 A8 L20 A9 L21 A10 A11 L23 C3 A12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 along normal blind 0.1 and against normal blind 1.7
sketch "Sketch21" plane through (0, 0, 5.8) normal (0, 0, 1) x axis (-1, 0, 0)
  line L1 (196, 29.35) -> (218, 29.35)
  line L2 (196, 27.75) -> (196, 29.35)
  line L3 (218, 27.75) -> (196, 27.75)
  line L4 (218, 29.35) -> (218, 27.75)
  line L5 (218, 29.35) -> (221, 29.35)
  line L6 (218, 27.75) -> (218, 29.35)
  line L7 (221, 27.75) -> (218, 27.75)
  line L8 (221, 29.35) -> (221, 27.75)
  line L9 (193, 29.35) -> (196, 29.35)
  line L10 (193, 27.75) -> (193, 29.35)
  line L11 (196, 27.75) -> (193, 27.75)
  line L12 (196, 29.35) -> (196, 27.75)
  line L13 (221, 29.35) -> (193, 29.35)
  line L14 (221, 26) -> (221, 29.35)
  line L15 (193, 26) -> (221, 26)
  line L16 (193, 29.35) -> (193, 26)
  horizontal L13
  vertical L14
  horizontal L15
  vertical L16
combine "Combine4"
component_from_bodies "Body->Comp5"
copy_paste "CopyPaste6"
joint "Assemble6" alignAngle 0 alignOffsetX 0 alignOffsetY 0 alignOffsetZ 0
copy_paste "CopyPaste7"
joint "Assemble7" alignAngle 0 alignOffsetX 0 alignOffsetY 0 alignOffsetZ 0
work_plane "WorkPlane3" AlongDistance 0
sketch "Sketch22" plane through (0, 0, 7.99) normal (0, 0, -1) x axis (-1, 0, 0)
  line L1 (196, -29.35) -> (193, -29.35)
  line L2 (193, -27.75) -> (193, -29.35)
  line L3 (193, -27.75) -> (196, -27.75)
  line L4 (196, -29.35) -> (196, -27.75)
  line L5 (196, -29.35) -> (218, -29.35)
  line L6 (196, -27.75) -> (196, -29.35)
  line L7 (218, -27.75) -> (196, -27.75)
  line L8 (218, -29.35) -> (218, -27.75)
  line L9 (221, -29.35) -> (218, -29.35)
  line L10 (218, -27.75) -> (218, -29.35)
  line L11 (218, -27.75) -> (221, -27.75)
  line L12 (221, -29.35) -> (221, -27.75)
  line L13 (163.6, -27.25) -> (250.4, -27.25)
  line L14 (155, -122.65) -> (155, -35.85)
  line L15 (250.4, -131.25) -> (163.6, -131.25)
  line L16 (259, -35.85) -> (259, -122.65)
  line L17 (260.5, -122.65) -> (260.5, -35.85)
  line L18 (163.6, -132.75) -> (250.4, -132.75)
  line L19 (153.5, -35.85) -> (153.5, -122.65)
  line L20 (250.4, -25.75) -> (163.6, -25.75)
  line L21 (207, -33.3135) -> (207, -27.75)
  line L22 (222, -27.25) -> (192, -27.25)
  line L23 (222, -31.45) -> (222, -27.25)
  line L24 (192, -31.45) -> (222, -31.45)
  line L25 (192, -27.25) -> (192, -31.45)
  line L26 (222, -31.45) -> (192, -27.25)
  line L27 (192, -31.45) -> (222, -27.25)
  line L28 (193, -27.25) -> (193, -27.75)
  line L29 (221, -27.25) -> (221, -27.75)
  line L30 (199.3064, -31.45) -> (199.3064, -29.35)
  line L31 (214.6936, -31.45) -> (214.6936, -29.35)
  line L32 (250.4, -27.25) -> (223.6065, -27.25)
  line L33 (259, -66.2577) -> (259, -35.85)
  line L34 (256, -66.2577) -> (259, -66.2577)
  line L35 (256, -35.85) -> (256, -66.2577)
  line L36 (223.6065, -30.25) -> (250.4, -30.25)
  line L37 (223.6065, -27.25) -> (223.6065, -30.25)
  line L38 (155, -35.85) -> (155, -66.2577)
  line L39 (190.3935, -27.25) -> (163.6, -27.25)
  line L40 (190.3935, -30.25) -> (190.3935, -27.25)
  line L41 (163.6, -30.25) -> (190.3935, -30.25)
  line L42 (158, -66.2577) -> (158, -35.85)
  line L43 (155, -66.2577) -> (158, -66.2577)
  line L44 (223.6065, -31.45) -> (223.6065, -30.25)
  line L45 (222, -31.45) -> (223.6065, -31.45)
  line L46 (190.3935, -31.45) -> (190.3935, -30.25)
  line L47 (192, -31.45) -> (190.3935, -31.45)
  line L48 (222, -27.75) -> (221, -27.75)
  line L49 (192, -27.75) -> (193, -27.75)
  arc A1 centre (163.6, -35.85) radius 8.6 clockwise from (155, -35.85) to (163.6, -27.25)
  arc A2 centre (163.6, -122.65) radius 8.6 clockwise from (163.6, -131.25) to (155, -122.65)
  arc A3 centre (250.4, -122.65) radius 8.6 clockwise from (259, -122.65) to (250.4, -131.25)
  arc A4 centre (250.4, -35.85) radius 8.6 clockwise from (250.4, -27.25) to (259, -35.85)
  arc A5 centre (250.4, -35.85) radius 10.1 clockwise from (250.4, -25.75) to (260.5, -35.85)
  arc A6 centre (250.4, -122.65) radius 10.1 clockwise from (260.5, -122.65) to (250.4, -132.75)
  arc A7 centre (163.6, -122.65) radius 10.1 clockwise from (163.6, -132.75) to (153.5, -122.65)
  arc A8 centre (163.6, -35.85) radius 10.1 clockwise from (153.5, -35.85) to (163.6, -25.75)
  arc A9 centre (250.4, -35.85) radius 8.6 clockwise from (250.4, -27.25) to (259, -35.85)
  arc A10 centre (250.4, -35.85) radius 5.6 clockwise from (250.4, -30.25) to (256, -35.85)
  arc A11 centre (163.6, -35.85) radius 8.6 clockwise from (155, -35.85) to (163.6, -27.25)
  arc A12 centre (163.6, -35.85) radius 5.6 clockwise from (158, -35.85) to (163.6, -30.25)
  point P34 (207, -27.75)
  point P40 (207, -29.35)
  point P41 (193, -27.25)
  point P42 (221, -27.25)
  point P43 (199.3064, -29.35)
  point P45 (214.6936, -29.35)
  point P44 (199.3064, -31.45)
  point P46 (214.6936, -31.45)
  point P69 (222, -27.75)
  point P70 (192, -27.75)
  point P38 (222, -31.45)
  point P39 (192, -31.45)
  midpoint L7 P34
  perpendicular L7 L21
  horizontal L22
  perpendicular L22 L23
  parallel L22 L24
  parallel L23 L25
  coincident L26 P40
  coincident L27 P40
  midpoint L5 P40
  coincident L13 P41
  coincident L22 P41
  coincident L13 P42
  coincident L22 P42
  perpendicular L13 L29
  symmetric L21 P43 P45
  symmetric L21 P44 P46
  perpendicular L24 L44
  perpendicular L23 L45
  perpendicular L24 L46
  perpendicular L25 L47
  coincident L23 P69
  perpendicular L23 L48
  coincident L25 P70
  perpendicular L25 L49
  dimension "d246" distance P38 P39 = 30
extrude "Extrude24" new body sketch "Sketch22" profile of L1 L2 L5 L9 L12 L13 L22 L23 L24 L25 L28 L29 L30 L31 along normal blind 11.5
extrude "Extrude25" new body sketch "Sketch22" profile of L1 L2 L3 L5 L7 L9 L11 L12 L13 L22 L23 L24 L25 L28 L29 L30 L31 L37 L40 L44 L45 L46 L47 L48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 against normal blind 3
extrude "Extrude26" new body sketch "Sketch22" profile of L1 L2 L3 L4 L5 L6 L7 L8 L9 L10 L11 L12 along normal blind 3 and against normal blind 3
extrude "Extrude7" cut sketch "Sketch1" profile of L7 C3 C4 against normal blind 38
sketch "Sketch2" plane through (0, 0, -10) normal (0, 0, -1) x axis (1, 0, 0)
  line L1 (4, 17.4451) -> (64, 17.4451)
  line L2 (4, -17.5549) -> (4, 17.4451)
  line L3 (64, -17.5549) -> (4, -17.5549)
  line L4 (64, 17.4451) -> (64, -17.5549)
  line L5 (34, 0) -> (64, -0.0549)
  line L6 (64, -0.0549) -> (34, 0)
  line L7 (21.3526, 13.7932) -> (20.2068, 12.6474)
  line L8 (46.6474, 13.7932) -> (21.3526, 13.7932)
  line L9 (47.7932, 12.6474) -> (46.6474, 13.7932)
  line L10 (47.7932, -12.6474) -> (47.7932, 12.6474)
  line L11 (46.6474, -13.7932) -> (47.7932, -12.6474)
  line L12 (21.3526, -13.7932) -> (46.6474, -13.7932)
  line L13 (20.2068, -12.6474) -> (21.3526, -13.7932)
  line L14 (20.2068, 12.6474) -> (20.2068, -12.6474)
  line L15 (50, -13.8287) -> (47.8287, -16)
  line L16 (50, 13.8287) -> (50, -13.8287)
  line L17 (47.8287, 16) -> (50, 13.8287)
  line L18 (20.1713, 16) -> (47.8287, 16)
  line L19 (18, 13.8287) -> (20.1713, 16)
  line L20 (18, -13.8287) -> (18, 13.8287)
  line L21 (20.1713, -16) -> (18, -13.8287)
  line L22 (47.8287, -16) -> (20.1713, -16)
  line L23 (34.62, -0.62) -> (36.12, -0.62)
  line L24 (34.62, -2.12) -> (34.62, -0.62)
  line L25 (33.38, -2.12) -> (34.62, -2.12)
  line L26 (33.38, -0.62) -> (33.38, -2.12)
  line L27 (31.88, -0.62) -> (33.38, -0.62)
  line L28 (31.88, 0.62) -> (31.88, -0.62)
  line L29 (33.38, 0.62) -> (31.88, 0.62)
  line L30 (33.38, 2.12) -> (33.38, 0.62)
  line L31 (34.62, 2.12) -> (33.38, 2.12)
  line L32 (34.62, 0.62) -> (34.62, 2.12)
  line L33 (36.12, 0.62) -> (34.62, 0.62)
  line L34 (36.12, -0.62) -> (36.12, 0.62)
  line L35 (36.12, 0.62) -> (36.12, -0.62)
  line L36 (34.62, 0.62) -> (36.12, 0.62)
  line L37 (34.62, 2.12) -> (34.62, 0.62)
  line L38 (33.38, 2.12) -> (34.62, 2.12)
  line L39 (33.38, 0.62) -> (33.38, 2.12)
  line L40 (31.88, 0.62) -> (33.38, 0.62)
  line L41 (31.88, -0.62) -> (31.88, 0.62)
  line L42 (33.38, -0.62) -> (31.88, -0.62)
  line L43 (33.38, -2.12) -> (33.38, -0.62)
  line L44 (34.62, -2.12) -> (33.38, -2.12)
  line L45 (34.62, -0.62) -> (34.62, -2.12)
  line L46 (36.12, -0.62) -> (34.62, -0.62)
  line L47 (50, -16) -> (18, -16)
  line L48 (50, 16) -> (50, -16)
  line L49 (18, 16) -> (50, 16)
  line L50 (18, -16) -> (18, 16)
  circle C1 centre (34, 0) radius 2.75
  point P6 (64, -0.0549)
  point P2 (64, 17.4451)
  point P5 (64, -17.5549)
  point P7 (34, 0)
  horizontal L1
  vertical L2
  horizontal L3
  vertical L4
  midpoint L4 P6
  horizontal L47
  vertical L48
  horizontal L49
  vertical L50
  dimension "d30" distance P2 P5 = 35
  dimension "d32" distance P6 P7 = 30
  dimension "d33" distance L2 P7 = 30
extrude "Extrude8" new body sketch "Sketch2" profile of L1 L2 L3 L4 L5 L6 L7 L8 L9 L10 L11 L12 L13 L14 L15 L16 L17 L18 L19 L20 L21 L22 L23 L24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 along normal blind 3
work_plane "WorkPlane1" AlongDistance 0
extrude "Extrude10" new body sketch "Sketch2" profile of L5 L6 L7 L8 L9 L10 L11 L12 L13 L14 L15 L16 L17 L18 L19 L20 L21 L22 L23 L24 L25 L26 L27 L28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 against normal blind 10 taper -25
chamfer "Chamfer1" distance 2
sketch "Sketch6" plane through (0, 0, 0) normal (0, 1, 0) x axis (1, 0, 0)
  line L1 (34, -125) -> (34, 10)
  circle C1 centre (34, -125) radius 125.3236
  point P3 (34, -125)
  point P4 (34, -125)
  vertical L1
  coincident P3 P4
sphere_primitive "SpherePrimitive2" sketch "Sketch6" Diameter 95 bodies "spher"
move_face "MoveFace2" TranslateX 0 TranslateY 0 TranslateZ -80
combine "Combine1"
shell "Shell1" innerThickness 2
extrude "Extrude11" add sketch "Sketch2" profile of L23 L24 L25 L26 L27 L28 L29 L30 L31 L32 L33 L34 C1 L35 L36 L37 L38 L39 L40 L41 L42 L43 L44 L45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 against normal blind 7
sketch "Sketch9" plane through (0, 0, -10) normal (0, 0, -1) x axis (1, 0, 0)
  line L1 (34.62, -0.62) -> (36.12, -0.62)
  line L2 (34.62, -2.12) -> (34.62, -0.62)
  line L3 (33.38, -2.12) -> (34.62, -2.12)
  line L4 (33.38, -0.62) -> (33.38, -2.12)
  line L5 (31.88, -0.62) -> (33.38, -0.62)
  line L6 (31.88, 0.62) -> (31.88, -0.62)
  line L7 (33.38, 0.62) -> (31.88, 0.62)
  line L8 (33.38, 2.12) -> (33.38, 0.62)
  line L9 (34.62, 2.12) -> (33.38, 2.12)
  line L10 (34.62, 0.62) -> (34.62, 2.12)
  line L11 (36.12, 0.62) -> (34.62, 0.62)
  line L12 (36.12, -0.62) -> (36.12, 0.62)
  circle C1 centre (34, 0) radius 2.75
  circle C2 centre (34, 0) radius 2.75
extrude "Extrude12" new body sketch "Sketch9" against normal blind 0.2
offset_faces "OffsetFaces1" distance 0
fillet "Fillet1" radius 1.5
copy_paste_bodies "CopyPasteBodies1"
component_from_bodies "Body->Comp1"
sketch "Sketch15" plane through (0, 0, -10) normal (0, 0, -1) x axis (1, 0, 0)
  line L1 (21.3526, -13.7932) -> (46.6474, -13.7932)
  line L2 (20.2068, -12.6474) -> (21.3526, -13.7932)
  line L3 (20.2068, 12.6474) -> (20.2068, -12.6474)
  line L4 (21.3526, 13.7932) -> (20.2068, 12.6474)
  line L5 (46.6474, 13.7932) -> (21.3526, 13.7932)
  line L6 (47.7932, 12.6474) -> (46.6474, 13.7932)
  line L7 (47.7932, -12.6474) -> (47.7932, 12.6474)
  line L8 (46.6474, -13.7932) -> (47.7932, -12.6474)
extrude "Extrude14" new body sketch "Sketch15" against normal blind 7 taper -25
offset_faces "OffsetFaces3" distance -5
combine "Combine2"
extrude "Extrude16" new body sketch "Sketch9" against normal blind 9
extrude "Extrude17" cut sketch "Sketch9" against normal blind 7.3
offset_faces "OffsetFaces5" distance -0.1
offset_faces "OffsetFaces6" distance -0.1
offset_faces "OffsetFaces7" distance -0.1
offset_faces "OffsetFaces8" distance -0.1
extrude "Extrude18" cut sketch "Sketch9" profile of L1 L2 L3 L4 L5 L6 L7 L8 L9 L10 L11 L12 against normal blind 7.3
